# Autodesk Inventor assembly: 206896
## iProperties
Created: 2008-01
Part Number: 206896
Document SubType Name: Assembly
Designer: jjohnson
Mass: 119.186 g
Surface Area: 559.788 cm^2
Volume: 62.8758 cm^3
Density: 1.89557 g/cm^3
Author: jjohnson
